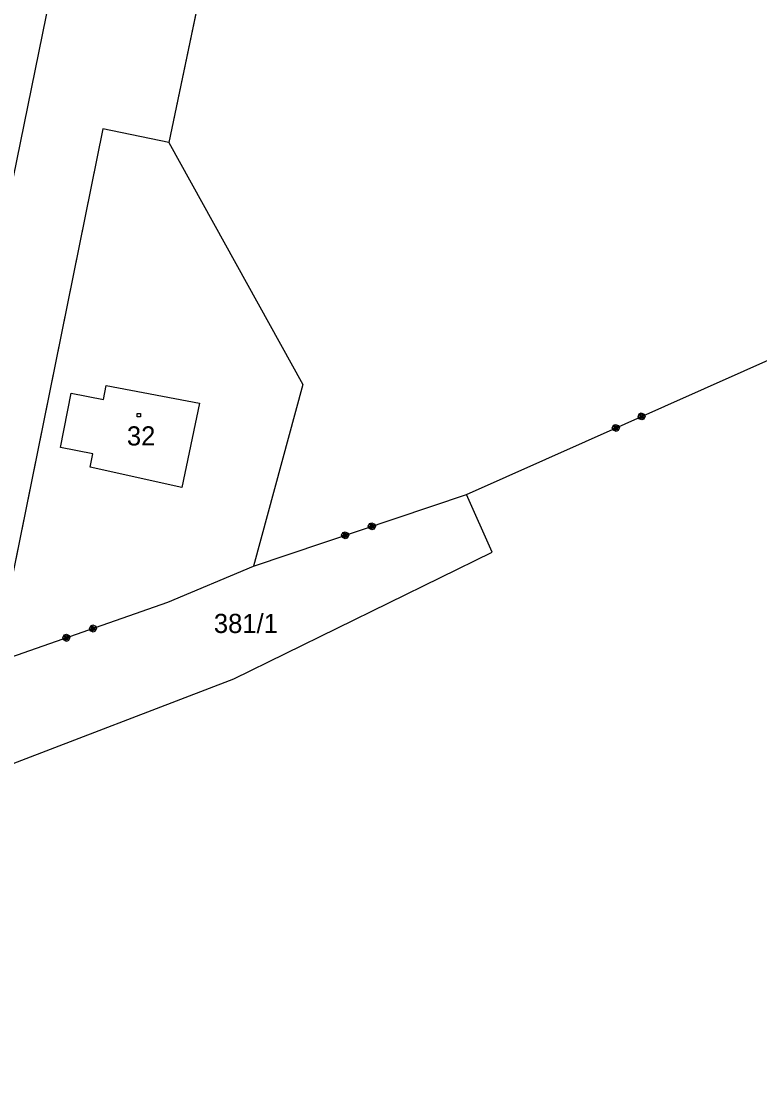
# Model space of a CAD drawing. Extents: x -866656 to -858817, y -1041816 to -1038653.
# Drawn here: x -864121.9 to -864056.3, y -1040985.3 to -1040891.7 of the extents above; entities that cross this region are included whole.
import ezdxf

# ---------------------------------------------------------------- set-up
doc = ezdxf.new("R2010")
doc.units = 0
for name, color, linetype in [('SZDC', 7, 'Continuous'), ('Vrstva 1', 7, 'Continuous'), ('Vrstva 2', 7, 'Continuous'), ('Vrstva 3', 7, 'Continuous'), ('Vrstva 53', 7, 'Continuous')]:
    doc.layers.add(name, color=color, linetype=linetype)

msp = doc.modelspace()

# ---------------------------------------------------------------- linework, layer by layer
at = {"layer": 'SZDC'}
msp.add_lwpolyline([(-864079.126, -1040751.242), (-864090.668, -1040816.123), (-864108.728, -1040902.454), (-864114.595, -1040901.24), (-864124.203, -1040948.655), (-864151.935, -1040958.113), (-864146.262, -1040929.775), (-864137.277, -1040882.02), (-864125.279, -1040805.207)], dxfattribs=at)
at = {"layer": 'Vrstva 1'}
for p, q in [((-864090.668, -1040816.123), (-864108.728, -1040902.454)), ((-864114.595, -1040901.24), (-864124.203, -1040948.655)), ((-864108.728, -1040902.454), (-864114.595, -1040901.24)), ((-864108.728, -1040902.454), (-864096.857, -1040923.928)), ((-864096.857, -1040923.928), (-864101.214, -1040940.055)), ((-864111.555, -1040926.503), (-864111.255, -1040926.503)), ((-864111.555, -1040926.803), (-864111.555, -1040926.503)), ((-864111.255, -1040926.803), (-864111.555, -1040926.803)), ((-864111.255, -1040926.503), (-864111.255, -1040926.803)), ((-864080.05, -1040938.84), (-864082.3, -1040933.7)), ((-864102.97, -1040950.08), (-864080.05, -1040938.84)), ((-864125.631, -1040958.765), (-864102.97, -1040950.08))]:
    msp.add_line(p, q, dxfattribs=at)
msp.add_lwpolyline([(-864190.897, -1041239.893), (-864187.654, -1041224.26), (-864179.077, -1041182.252), (-864176.192, -1041168.165), (-864167.631, -1041126.213), (-864158.946, -1041083.668), (-864157.987, -1041079.013), (-864156.213, -1041070.305), (-864147.519, -1041027.821), (-864138.927, -1040985.783), (-864136.16, -1040972.299), (-864133.068, -1040957.148), (-864132.451, -1040954.143), (-864131.095, -1040947.46), (-864122.536, -1040905.522), (-864114.141, -1040864.418), (-864106.236, -1040825.758)], dxfattribs=at)
at = {"layer": 'Vrstva 2'}
for p, q in [((-864114.536, -1040925.264), (-864114.29, -1040924.021)), ((-864114.29, -1040924.021), (-864106.023, -1040925.6)), ((-864118.36, -1040929.529), (-864117.406, -1040924.698)), ((-864117.406, -1040924.698), (-864114.536, -1040925.264)), ((-864106.023, -1040925.6), (-864107.571, -1040933.08)), ((-864115.49, -1040930.095), (-864118.36, -1040929.529)), ((-864115.726, -1040931.291), (-864115.49, -1040930.095)), ((-864107.571, -1040933.08), (-864115.726, -1040931.291))]:
    msp.add_line(p, q, dxfattribs=at)
at = {"layer": 'Vrstva 3'}
for p, q in [((-864082.3, -1040933.7), (-864053.26, -1040920.75)), ((-864082.3, -1040933.7), (-864053.26, -1040920.75)), ((-864067.09, -1040926.807), (-864066.988, -1040926.543)), ((-864067.09, -1040926.807), (-864066.988, -1040926.543)), ((-864067.008, -1040926.99), (-864067.09, -1040926.807)), ((-864067.008, -1040926.99), (-864067.09, -1040926.807)), ((-864066.998, -1040926.767), (-864066.917, -1040926.949)), ((-864066.998, -1040926.767), (-864066.917, -1040926.949)), ((-864066.988, -1040926.543), (-864066.806, -1040926.462)), ((-864066.988, -1040926.543), (-864066.806, -1040926.462)), ((-864066.948, -1040926.635), (-864066.765, -1040926.553)), ((-864066.948, -1040926.635), (-864066.765, -1040926.553)), ((-864066.785, -1040927), (-864066.948, -1040926.635)), ((-864066.785, -1040927), (-864066.948, -1040926.635)), ((-864066.856, -1040926.594), (-864066.693, -1040926.959)), ((-864066.856, -1040926.594), (-864066.693, -1040926.959)), ((-864066.806, -1040926.462), (-864066.542, -1040926.563)), ((-864066.806, -1040926.462), (-864066.542, -1040926.563)), ((-864066.765, -1040926.553), (-864066.602, -1040926.918)), ((-864066.765, -1040926.553), (-864066.602, -1040926.918)), ((-864066.551, -1040926.786), (-864066.633, -1040926.604)), ((-864066.551, -1040926.786), (-864066.633, -1040926.604)), ((-864066.602, -1040926.918), (-864066.551, -1040926.786)), ((-864066.602, -1040926.918), (-864066.551, -1040926.786)), ((-864066.46, -1040926.746), (-864066.561, -1040927.01)), ((-864066.46, -1040926.746), (-864066.561, -1040927.01)), ((-864066.542, -1040926.563), (-864066.46, -1040926.746)), ((-864066.542, -1040926.563), (-864066.46, -1040926.746)), ((-864069.373, -1040927.826), (-864069.272, -1040927.561)), ((-864069.373, -1040927.826), (-864069.272, -1040927.561)), ((-864069.282, -1040927.785), (-864069.2, -1040927.967)), ((-864069.282, -1040927.785), (-864069.2, -1040927.967)), ((-864069.272, -1040927.561), (-864069.089, -1040927.48)), ((-864069.272, -1040927.561), (-864069.089, -1040927.48)), ((-864069.231, -1040927.653), (-864069.048, -1040927.571)), ((-864069.231, -1040927.653), (-864069.048, -1040927.571)), ((-864069.068, -1040928.018), (-864069.231, -1040927.653)), ((-864069.068, -1040928.018), (-864069.231, -1040927.653)), ((-864069.14, -1040927.612), (-864068.977, -1040927.977)), ((-864069.14, -1040927.612), (-864068.977, -1040927.977)), ((-864069.089, -1040927.48), (-864068.825, -1040927.581)), ((-864069.089, -1040927.48), (-864068.825, -1040927.581)), ((-864069.048, -1040927.571), (-864068.885, -1040927.937)), ((-864069.048, -1040927.571), (-864068.885, -1040927.937)), ((-864068.835, -1040927.805), (-864068.916, -1040927.622)), ((-864068.835, -1040927.805), (-864068.916, -1040927.622)), ((-864068.743, -1040927.764), (-864068.845, -1040928.028)), ((-864068.743, -1040927.764), (-864068.845, -1040928.028)), ((-864068.825, -1040927.581), (-864068.743, -1040927.764)), ((-864068.825, -1040927.581), (-864068.743, -1040927.764)), ((-864066.744, -1040927.091), (-864067.008, -1040926.99)), ((-864066.744, -1040927.091), (-864067.008, -1040926.99)), ((-864066.917, -1040926.949), (-864066.785, -1040927)), ((-864066.917, -1040926.949), (-864066.785, -1040927)), ((-864066.561, -1040927.01), (-864066.744, -1040927.091)), ((-864066.561, -1040927.01), (-864066.744, -1040927.091)), ((-864069.291, -1040928.008), (-864069.373, -1040927.826)), ((-864069.291, -1040928.008), (-864069.373, -1040927.826)), ((-864069.027, -1040928.109), (-864069.291, -1040928.008)), ((-864069.027, -1040928.109), (-864069.291, -1040928.008)), ((-864069.2, -1040927.967), (-864069.068, -1040928.018)), ((-864069.2, -1040927.967), (-864069.068, -1040928.018)), ((-864068.845, -1040928.028), (-864069.027, -1040928.109)), ((-864068.845, -1040928.028), (-864069.027, -1040928.109)), ((-864068.885, -1040927.937), (-864068.835, -1040927.805)), ((-864068.885, -1040927.937), (-864068.835, -1040927.805)), ((-864101.214, -1040940.055), (-864082.3, -1040933.7)), ((-864101.214, -1040940.055), (-864082.3, -1040933.7)), ((-864090.904, -1040936.274), (-864090.715, -1040936.211)), ((-864090.904, -1040936.274), (-864090.715, -1040936.211)), ((-864090.715, -1040936.211), (-864090.462, -1040936.336)), ((-864090.715, -1040936.211), (-864090.462, -1040936.336)), ((-864093.4, -1040937.324), (-864093.274, -1040937.07)), ((-864093.4, -1040937.324), (-864093.274, -1040937.07)), ((-864093.274, -1040937.07), (-864093.085, -1040937.007)), ((-864093.274, -1040937.07), (-864093.085, -1040937.007)), ((-864093.242, -1040937.165), (-864093.053, -1040937.102)), ((-864093.242, -1040937.165), (-864093.053, -1040937.102)), ((-864093.148, -1040937.133), (-864093.02, -1040937.513)), ((-864093.148, -1040937.133), (-864093.02, -1040937.513)), ((-864093.085, -1040937.007), (-864092.831, -1040937.133)), ((-864093.085, -1040937.007), (-864092.831, -1040937.133)), ((-864093.053, -1040937.102), (-864092.925, -1040937.481)), ((-864093.053, -1040937.102), (-864092.925, -1040937.481)), ((-864092.831, -1040937.133), (-864092.768, -1040937.322)), ((-864092.831, -1040937.133), (-864092.768, -1040937.322)), ((-864091.03, -1040936.527), (-864090.904, -1040936.274)), ((-864091.03, -1040936.527), (-864090.904, -1040936.274)), ((-864090.967, -1040936.717), (-864091.03, -1040936.527)), ((-864090.967, -1040936.717), (-864091.03, -1040936.527)), ((-864090.713, -1040936.843), (-864090.967, -1040936.717)), ((-864090.713, -1040936.843), (-864090.967, -1040936.717)), ((-864090.935, -1040936.496), (-864090.872, -1040936.685)), ((-864090.935, -1040936.496), (-864090.872, -1040936.685)), ((-864090.873, -1040936.369), (-864090.683, -1040936.305)), ((-864090.873, -1040936.369), (-864090.683, -1040936.305)), ((-864090.745, -1040936.748), (-864090.873, -1040936.369)), ((-864090.745, -1040936.748), (-864090.873, -1040936.369)), ((-864090.872, -1040936.685), (-864090.745, -1040936.748)), ((-864090.872, -1040936.685), (-864090.745, -1040936.748)), ((-864090.778, -1040936.337), (-864090.65, -1040936.716)), ((-864090.778, -1040936.337), (-864090.65, -1040936.716)), ((-864090.524, -1040936.779), (-864090.713, -1040936.843)), ((-864090.524, -1040936.779), (-864090.713, -1040936.843)), ((-864090.683, -1040936.305), (-864090.556, -1040936.684)), ((-864090.683, -1040936.305), (-864090.556, -1040936.684)), ((-864090.493, -1040936.558), (-864090.556, -1040936.368)), ((-864090.493, -1040936.558), (-864090.556, -1040936.368)), ((-864090.556, -1040936.684), (-864090.493, -1040936.558)), ((-864090.556, -1040936.684), (-864090.493, -1040936.558)), ((-864090.398, -1040936.526), (-864090.524, -1040936.779)), ((-864090.398, -1040936.526), (-864090.524, -1040936.779)), ((-864090.462, -1040936.336), (-864090.398, -1040936.526)), ((-864090.462, -1040936.336), (-864090.398, -1040936.526)), ((-864093.336, -1040937.513), (-864093.4, -1040937.324)), ((-864093.336, -1040937.513), (-864093.4, -1040937.324)), ((-864093.083, -1040937.639), (-864093.336, -1040937.513)), ((-864093.083, -1040937.639), (-864093.336, -1040937.513)), ((-864093.305, -1040937.292), (-864093.242, -1040937.481)), ((-864093.305, -1040937.292), (-864093.242, -1040937.481)), ((-864093.115, -1040937.544), (-864093.242, -1040937.165)), ((-864093.115, -1040937.544), (-864093.242, -1040937.165)), ((-864093.242, -1040937.481), (-864093.115, -1040937.544)), ((-864093.242, -1040937.481), (-864093.115, -1040937.544)), ((-864092.894, -1040937.576), (-864093.083, -1040937.639)), ((-864092.894, -1040937.576), (-864093.083, -1040937.639)), ((-864092.862, -1040937.354), (-864092.926, -1040937.164)), ((-864092.862, -1040937.354), (-864092.926, -1040937.164)), ((-864092.925, -1040937.481), (-864092.862, -1040937.354)), ((-864092.925, -1040937.481), (-864092.862, -1040937.354)), ((-864092.768, -1040937.322), (-864092.894, -1040937.576)), ((-864092.768, -1040937.322), (-864092.894, -1040937.576)), ((-864108.814, -1040943.274), (-864101.214, -1040940.055)), ((-864108.814, -1040943.274), (-864101.214, -1040940.055)), ((-864124.203, -1040948.655), (-864108.814, -1040943.274)), ((-864124.203, -1040948.655), (-864108.814, -1040943.274)), ((-864115.786, -1040945.606), (-864115.664, -1040945.351)), ((-864115.786, -1040945.606), (-864115.664, -1040945.351)), ((-864115.692, -1040945.573), (-864115.626, -1040945.762)), ((-864115.692, -1040945.573), (-864115.626, -1040945.762)), ((-864115.664, -1040945.351), (-864115.475, -1040945.285)), ((-864115.664, -1040945.351), (-864115.475, -1040945.285)), ((-864115.631, -1040945.446), (-864115.442, -1040945.38)), ((-864115.631, -1040945.446), (-864115.442, -1040945.38)), ((-864115.498, -1040945.823), (-864115.631, -1040945.446)), ((-864115.498, -1040945.823), (-864115.631, -1040945.446)), ((-864115.536, -1040945.413), (-864115.404, -1040945.79)), ((-864115.536, -1040945.413), (-864115.404, -1040945.79)), ((-864115.475, -1040945.285), (-864115.22, -1040945.408)), ((-864115.475, -1040945.285), (-864115.22, -1040945.408)), ((-864115.442, -1040945.38), (-864115.31, -1040945.757)), ((-864115.442, -1040945.38), (-864115.31, -1040945.757)), ((-864115.248, -1040945.63), (-864115.314, -1040945.441)), ((-864115.248, -1040945.63), (-864115.314, -1040945.441)), ((-864115.22, -1040945.408), (-864115.154, -1040945.597)), ((-864115.22, -1040945.408), (-864115.154, -1040945.597)), ((-864118.146, -1040946.431), (-864118.023, -1040946.177)), ((-864118.146, -1040946.431), (-864118.023, -1040946.177)), ((-864118.08, -1040946.62), (-864118.146, -1040946.431)), ((-864118.08, -1040946.62), (-864118.146, -1040946.431)), ((-864118.052, -1040946.398), (-864117.986, -1040946.587)), ((-864118.052, -1040946.398), (-864117.986, -1040946.587)), ((-864118.023, -1040946.177), (-864117.835, -1040946.111)), ((-864118.023, -1040946.177), (-864117.835, -1040946.111)), ((-864117.99, -1040946.271), (-864117.802, -1040946.205)), ((-864117.99, -1040946.271), (-864117.802, -1040946.205)), ((-864117.858, -1040946.649), (-864117.99, -1040946.271)), ((-864117.858, -1040946.649), (-864117.99, -1040946.271)), ((-864117.896, -1040946.238), (-864117.764, -1040946.616)), ((-864117.896, -1040946.238), (-864117.764, -1040946.616)), ((-864117.835, -1040946.111), (-864117.58, -1040946.233)), ((-864117.835, -1040946.111), (-864117.58, -1040946.233)), ((-864117.802, -1040946.205), (-864117.67, -1040946.583)), ((-864117.802, -1040946.205), (-864117.67, -1040946.583)), ((-864117.608, -1040946.455), (-864117.674, -1040946.266)), ((-864117.608, -1040946.455), (-864117.674, -1040946.266)), ((-864117.67, -1040946.583), (-864117.608, -1040946.455)), ((-864117.67, -1040946.583), (-864117.608, -1040946.455)), ((-864117.514, -1040946.422), (-864117.637, -1040946.677)), ((-864117.514, -1040946.422), (-864117.637, -1040946.677)), ((-864117.58, -1040946.233), (-864117.514, -1040946.422)), ((-864117.58, -1040946.233), (-864117.514, -1040946.422)), ((-864115.72, -1040945.795), (-864115.786, -1040945.606)), ((-864115.72, -1040945.795), (-864115.786, -1040945.606)), ((-864115.465, -1040945.918), (-864115.72, -1040945.795)), ((-864115.465, -1040945.918), (-864115.72, -1040945.795)), ((-864115.626, -1040945.762), (-864115.498, -1040945.823)), ((-864115.626, -1040945.762), (-864115.498, -1040945.823)), ((-864115.277, -1040945.852), (-864115.465, -1040945.918)), ((-864115.277, -1040945.852), (-864115.465, -1040945.918)), ((-864115.31, -1040945.757), (-864115.248, -1040945.63)), ((-864115.31, -1040945.757), (-864115.248, -1040945.63)), ((-864115.154, -1040945.597), (-864115.277, -1040945.852)), ((-864115.154, -1040945.597), (-864115.277, -1040945.852)), ((-864117.825, -1040946.743), (-864118.08, -1040946.62)), ((-864117.825, -1040946.743), (-864118.08, -1040946.62)), ((-864117.986, -1040946.587), (-864117.858, -1040946.649)), ((-864117.986, -1040946.587), (-864117.858, -1040946.649)), ((-864117.637, -1040946.677), (-864117.825, -1040946.743)), ((-864117.637, -1040946.677), (-864117.825, -1040946.743))]:
    msp.add_line(p, q, dxfattribs=at)
at = {"layer": 'Vrstva 53'}
msp.add_lwpolyline([(-864163.471, -1040355.801), (-864153.108, -1040402.253), (-864151.773, -1040408.236), (-864141.636, -1040383.5), (-864136.164, -1040395.654), (-864121.344, -1040428.573), (-864124.994, -1040437.136), (-864137.005, -1040440.857), (-864126.473, -1040480.602), (-864126.25, -1040482.627), (-864122.508, -1040516.53), (-864121.023, -1040529.985), (-864108.772, -1040562.648), (-864093.709, -1040623.913), (-864080.868, -1040663.902), (-864070.496, -1040699.085), (-864073.496, -1040728.47), (-864078.356, -1040748.127), (-864079.126, -1040751.243), (-864090.668, -1040816.124), (-864108.728, -1040902.455), (-864114.595, -1040901.241), (-864124.203, -1040948.655)], dxfattribs=at)

# ---------------------------------------------------------------- texts
at = {"layer": 'Vrstva 1'}
for s, p in [('32', (-864112.462, -1040929.356)), ('381/1', (-864104.74, -1040946.002))]:
    msp.add_text(s, height=1.7, dxfattribs=at).set_placement(p)

doc.saveas('drawing.dxf')
